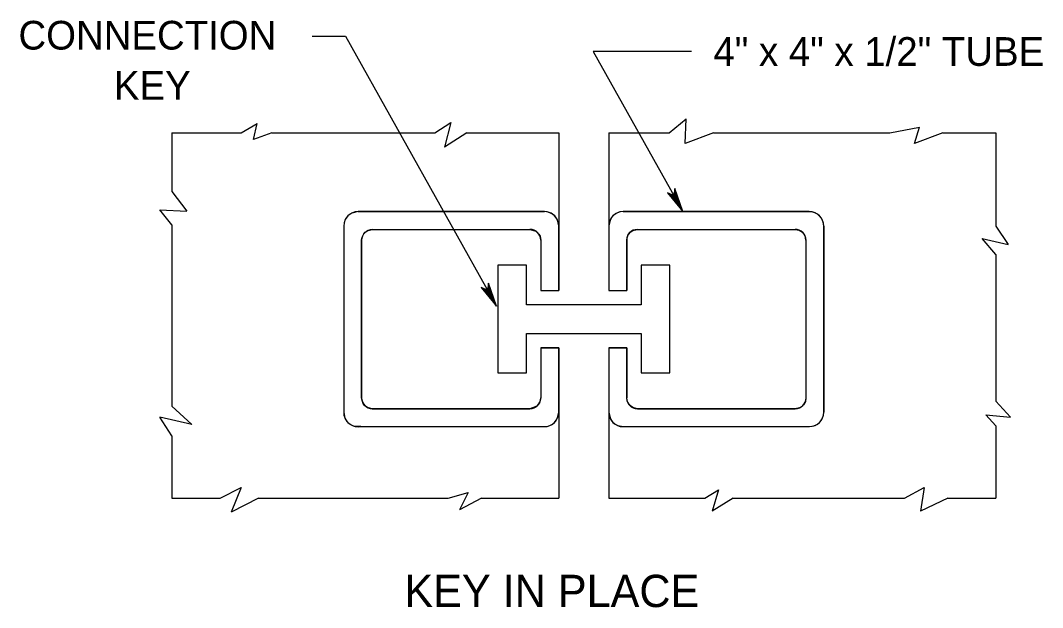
# Model space of a CAD drawing. Extents: x 499866 to 500993, y 499985 to 500645.
# Drawn here: x 500422 to 500564.5, y 500297.1 to 500379 of the extents above; entities that cross this region are included whole.
import ezdxf

# ---------------------------------------------------------------- set-up
doc = ezdxf.new("R2010")
doc.units = 0
for name, color, linetype in [('24', 7, 'Continuous'), ('5', 7, 'Continuous'), ('60', 7, 'Continuous')]:
    doc.layers.add(name, color=color, linetype=linetype)

msp = doc.modelspace()

# ---------------------------------------------------------------- linework, layer by layer
at = {"layer": '24'}
for points in [[(500514.32, 500352.34), (500513.2, 500355.55), (500513.07, 500354.57), (500512.18, 500354.96), (500514.32, 500352.34), (500514.21, 500352.53), (500513.21, 500355.45), (500513.1, 500354.51), (500512.29, 500354.87), (500514.14, 500352.63), (500514.1, 500352.74), (500513.23, 500355.23), (500513.11, 500354.49), (500512.42, 500354.79), (500514.08, 500352.78), (500514.01, 500352.87), (500513.25, 500355.05), (500513.13, 500354.48), (500512.55, 500354.67), (500513.85, 500353.15), (500513.76, 500353.32), (500513.26, 500354.87), (500513.15, 500354.45), (500512.7, 500354.58), (500513.75, 500353.36), (500513.67, 500353.52), (500513.27, 500354.66), (500513.18, 500354.35), (500512.86, 500354.45), (500513.59, 500353.66), (500513.52, 500353.81), (500513.29, 500354.51), (500513.2, 500354.32), (500512.95, 500354.41), (500513.46, 500353.88), (500513.33, 500354.34), (500513.25, 500354.22), (500513.04, 500354.34), (500513.39, 500353.97), (500513.3, 500354.28), (500513.28, 500354.12), (500513.15, 500354.22), (500513.31, 500354.14), (500513.29, 500354.21)], [(500488.33, 500339.15), (500487.21, 500342.37), (500487.08, 500341.38), (500486.19, 500341.78), (500488.33, 500339.15), (500488.21, 500339.34), (500487.21, 500342.26), (500487.1, 500341.32), (500486.29, 500341.68), (500488.14, 500339.44), (500488.1, 500339.55), (500487.24, 500342.04), (500487.11, 500341.3), (500486.42, 500341.61), (500488.08, 500339.59), (500488.01, 500339.68), (500487.26, 500341.87), (500487.13, 500341.29), (500486.55, 500341.48), (500487.85, 500339.96), (500487.76, 500340.13), (500487.27, 500341.68), (500487.16, 500341.26), (500486.7, 500341.39), (500487.76, 500340.17), (500487.68, 500340.33), (500487.27, 500341.47), (500487.18, 500341.16), (500486.86, 500341.26), (500487.59, 500340.47), (500487.52, 500340.62), (500487.29, 500341.32), (500487.21, 500341.13), (500486.96, 500341.22), (500487.46, 500340.69), (500487.33, 500341.15), (500487.25, 500341.03), (500487.04, 500341.15), (500487.39, 500340.78), (500487.31, 500341.09), (500487.28, 500340.93), (500487.16, 500341.03), (500487.31, 500340.95), (500487.29, 500341.02)]]:
    msp.add_lwpolyline(points, dxfattribs=at)
at = {"layer": '5'}
for p, q in [((500479.73, 500363.33), (500481.96, 500364.78)), ((500481.96, 500364.78), (500481.1, 500361.34)), ((500512.4, 500363.33), (500514.81, 500365.29)), ((500514.64, 500361.85), (500514.81, 500365.29)), ((500443.05, 500363.33), (500452.73, 500363.33)), ((500443.05, 500363.33), (500443.05, 500355.15)), ((500452.73, 500363.33), (500454.96, 500364.6)), ((500454.45, 500362.37), (500454.96, 500364.6)), ((500457.03, 500363.33), (500454.45, 500362.37)), ((500457.03, 500363.33), (500479.73, 500363.33)), ((500484.2, 500363.33), (500481.1, 500361.34)), ((500484.2, 500363.33), (500497.01, 500363.33)), ((500497.01, 500363.33), (500497.01, 500341.35)), ((500504, 500363.33), (500504, 500341.35)), ((500504, 500363.33), (500512.4, 500363.33)), ((500518.59, 500363.33), (500514.64, 500361.85)), ((500518.59, 500363.33), (500543.19, 500363.33)), ((500543.19, 500363.33), (500547.31, 500364.09)), ((500546.62, 500361.85), (500547.31, 500364.09)), ((500550.58, 500363.33), (500546.62, 500361.85)), ((500550.58, 500363.33), (500557.96, 500363.33)), ((500557.96, 500363.33), (500557.96, 500350.33)), ((500443.05, 500355.15), (500445.16, 500352.39)), ((500443.05, 500350.5), (500441.38, 500352.57)), ((500441.38, 500352.57), (500445.16, 500352.39)), ((500469.04, 500352.34), (500495.02, 500352.34)), ((500506, 500352.34), (500531.96, 500352.34)), ((500443.05, 500350.5), (500443.05, 500325.22)), ((500467.03, 500350.33), (500467.03, 500324.35)), ((500471.03, 500349.84), (500493.02, 500349.84)), ((500507.95, 500349.84), (500530, 500349.84)), ((500533.98, 500350.33), (500533.98, 500324.37)), ((500557.96, 500350.33), (500559.69, 500347.75)), ((500469.53, 500348.34), (500469.53, 500326.37)), ((500494.51, 500348.36), (500494.51, 500341.35)), ((500506.5, 500348.35), (500506.5, 500341.35)), ((500531.48, 500348.36), (500531.48, 500326.38)), ((500557.96, 500346.38), (500556.08, 500348.61)), ((500556.08, 500348.61), (500559.69, 500347.75)), ((500557.96, 500346.38), (500557.96, 500325.91)), ((500494.51, 500341.35), (500497.01, 500341.35)), ((500504, 500341.35), (500506.5, 500341.35)), ((500494.51, 500333.36), (500497.01, 500333.36)), ((500494.51, 500333.36), (500494.51, 500326.36)), ((500497.01, 500333.36), (500497.01, 500324.39)), ((500504, 500333.36), (500506.5, 500333.36)), ((500504, 500333.36), (500504, 500312.37)), ((500506.5, 500333.36), (500506.5, 500326.38)), ((500443.05, 500325.22), (500445.85, 500322.64)), ((500471.01, 500324.86), (500493.01, 500324.86)), ((500507.98, 500324.86), (500530, 500324.86)), ((500557.96, 500325.91), (500560.04, 500323.67)), ((500443.05, 500321.1), (500441.38, 500323.67)), ((500445.85, 500322.64), (500441.38, 500323.67)), ((500497.01, 500324.39), (500497.01, 500312.37)), ((500557.96, 500322.47), (500556.6, 500324.02)), ((500556.6, 500324.02), (500560.04, 500323.67)), ((500469.01, 500322.37), (500495.01, 500322.37)), ((500506, 500322.37), (500531.98, 500322.37)), ((500557.96, 500322.47), (500557.96, 500312.37)), ((500443.05, 500321.1), (500443.05, 500312.37)), ((500449.8, 500312.37), (500452.73, 500313.87)), ((500452.73, 500313.87), (500451.35, 500310.43)), ((500517.39, 500312.37), (500519.28, 500313.53)), ((500519.28, 500313.53), (500518.42, 500310.6)), ((500545.25, 500312.37), (500548, 500313.87)), ((500548, 500313.87), (500547.48, 500310.6)), ((500443.05, 500312.37), (500449.8, 500312.37)), ((500455.13, 500312.37), (500451.35, 500310.43)), ((500455.13, 500312.37), (500481.62, 500312.37)), ((500481.62, 500312.37), (500484.37, 500313.18)), ((500484.37, 500313.18), (500483.17, 500310.78)), ((500486.26, 500312.37), (500483.17, 500310.78)), ((500486.26, 500312.37), (500497.01, 500312.37)), ((500504, 500312.37), (500517.39, 500312.37)), ((500521.34, 500312.37), (500518.42, 500310.6)), ((500521.34, 500312.37), (500545.25, 500312.37)), ((500551.27, 500312.37), (500547.48, 500310.6)), ((500551.27, 500312.37), (500557.96, 500312.37))]:
    msp.add_line(p, q, dxfattribs=at)
for points in [[(500462.64, 500376.78), (500467.27, 500376.78), (500488.33, 500339.15)], [(500515.53, 500374.66), (500501.81, 500374.66), (500514.32, 500352.34)]]:
    msp.add_lwpolyline(points, dxfattribs=at)
for centre, radius, start, end in [((500469.04, 500350.34), 2, 90, 180), ((500495.02, 500350.34), 2, 0, 90), ((500506, 500350.34), 2, 90, 180), ((500531.98, 500350.33), 2, 0, 90), ((500471.03, 500348.34), 1.5, 90, 180), ((500493.01, 500348.36), 1.5, 0, 90), ((500508, 500348.35), 1.5, 90, 180), ((500529.98, 500348.36), 1.5, 0, 90), ((500471.03, 500326.37), 1.5, 180, 270), ((500493.01, 500326.36), 1.5, 270, 0), ((500507.98, 500326.36), 1.5, 180, 270), ((500530, 500326.36), 1.5, 270, 0), ((500469.03, 500324.35), 2, 180, 270), ((500495.01, 500324.36), 2, 270, 0), ((500506, 500324.36), 2, 180, 270), ((500531.98, 500324.37), 2, 270, 0)]:
    msp.add_arc(centre, radius, start, end, dxfattribs=at)
at = {"layer": '60'}
for points in [[(500493.02, 500349.84), (500493.83, 500349.61), (500494.24, 500349.21), (500494.41, 500348.91), (500494.51, 500348.36), (500494.51, 500341.35), (500497.01, 500341.35), (500497.02, 500350.34), (500496.84, 500351.19), (500496.46, 500351.73), (500495.97, 500352.11), (500495.56, 500352.27), (500495.02, 500352.34), (500469.04, 500352.34), (500468.16, 500352.14), (500467.6, 500351.73), (500467.26, 500351.25), (500467.09, 500350.76), (500467.03, 500350.33), (500467.03, 500324.35), (500467.2, 500323.54), (500467.48, 500323.09), (500467.89, 500322.71), (500468.36, 500322.47), (500470.49, 500322.37), (500493.83, 500322.37), (500495.54, 500322.44), (500496.08, 500322.68), (500496.56, 500323.1), (500496.85, 500323.57), (500497.01, 500324.39), (500497.01, 500333.36), (500494.51, 500333.36), (500494.51, 500326.36), (500494.35, 500325.7), (500493.97, 500325.21), (500493.01, 500324.86), (500471.01, 500324.86), (500470.33, 500325.04), (500469.95, 500325.32), (500469.73, 500325.61), (500469.53, 500326.37), (500469.53, 500348.34), (500469.6, 500348.79), (500469.82, 500349.23), (500470.02, 500349.46), (500470.39, 500349.7), (500471.03, 500349.84)], [(500506, 500352.34), (500505.53, 500352.29), (500504.89, 500352.01), (500504.42, 500351.57), (500504.17, 500351.14), (500504, 500350.34), (500504, 500341.35), (500506.5, 500341.35), (500506.5, 500348.35), (500506.56, 500348.75), (500506.72, 500349.13), (500506.99, 500349.46), (500507.34, 500349.7), (500507.95, 500349.84), (500530, 500349.84), (500530.53, 500349.75), (500531, 500349.46), (500531.22, 500349.2), (500531.39, 500348.86), (500531.48, 500348.36), (500531.48, 500326.38), (500531.41, 500325.85), (500531.16, 500325.42), (500530.86, 500325.14), (500530.58, 500324.98), (500530, 500324.86), (500507.98, 500324.86), (500507.33, 500325.01), (500506.84, 500325.38), (500506.55, 500325.9), (500506.5, 500326.38), (500506.5, 500333.36), (500504, 500333.36), (500504, 500324.36), (500504.23, 500323.44), (500504.49, 500323.06), (500504.91, 500322.69), (500505.24, 500322.52), (500506, 500322.37), (500531.98, 500322.37), (500532.61, 500322.47), (500533.13, 500322.73), (500533.49, 500323.05), (500533.77, 500323.46), (500533.94, 500323.94), (500533.98, 500324.37), (500533.98, 500350.33), (500533.91, 500350.86), (500533.65, 500351.44), (500533.12, 500351.98), (500532.74, 500352.18), (500532.31, 500352.3), (500531.96, 500352.34)], [(500488.51, 500344.85), (500488.51, 500329.86), (500492.51, 500329.86), (500492.51, 500335.36), (500508.5, 500335.36), (500508.5, 500329.86), (500512.5, 500329.86), (500512.5, 500344.85), (500508.5, 500344.85), (500508.5, 500339.35), (500492.51, 500339.35), (500492.51, 500344.85)]]:
    msp.add_lwpolyline(points, close=True, dxfattribs=at)

# ---------------------------------------------------------------- texts
at = {"layer": '5'}
for s, height, p in [('CONNECTION', 4, (500421.68, 500374.93)), ('4" x 4" x 1/2" TUBE', 4, (500518.59, 500372.66)), ('KEY', 4, (500434.99, 500367.93)), ('KEY IN PLACE', 4.5, (500475.49, 500297.21))]:
    msp.add_text(s, height=height, dxfattribs=at).set_placement(p)

doc.saveas('drawing.dxf')
